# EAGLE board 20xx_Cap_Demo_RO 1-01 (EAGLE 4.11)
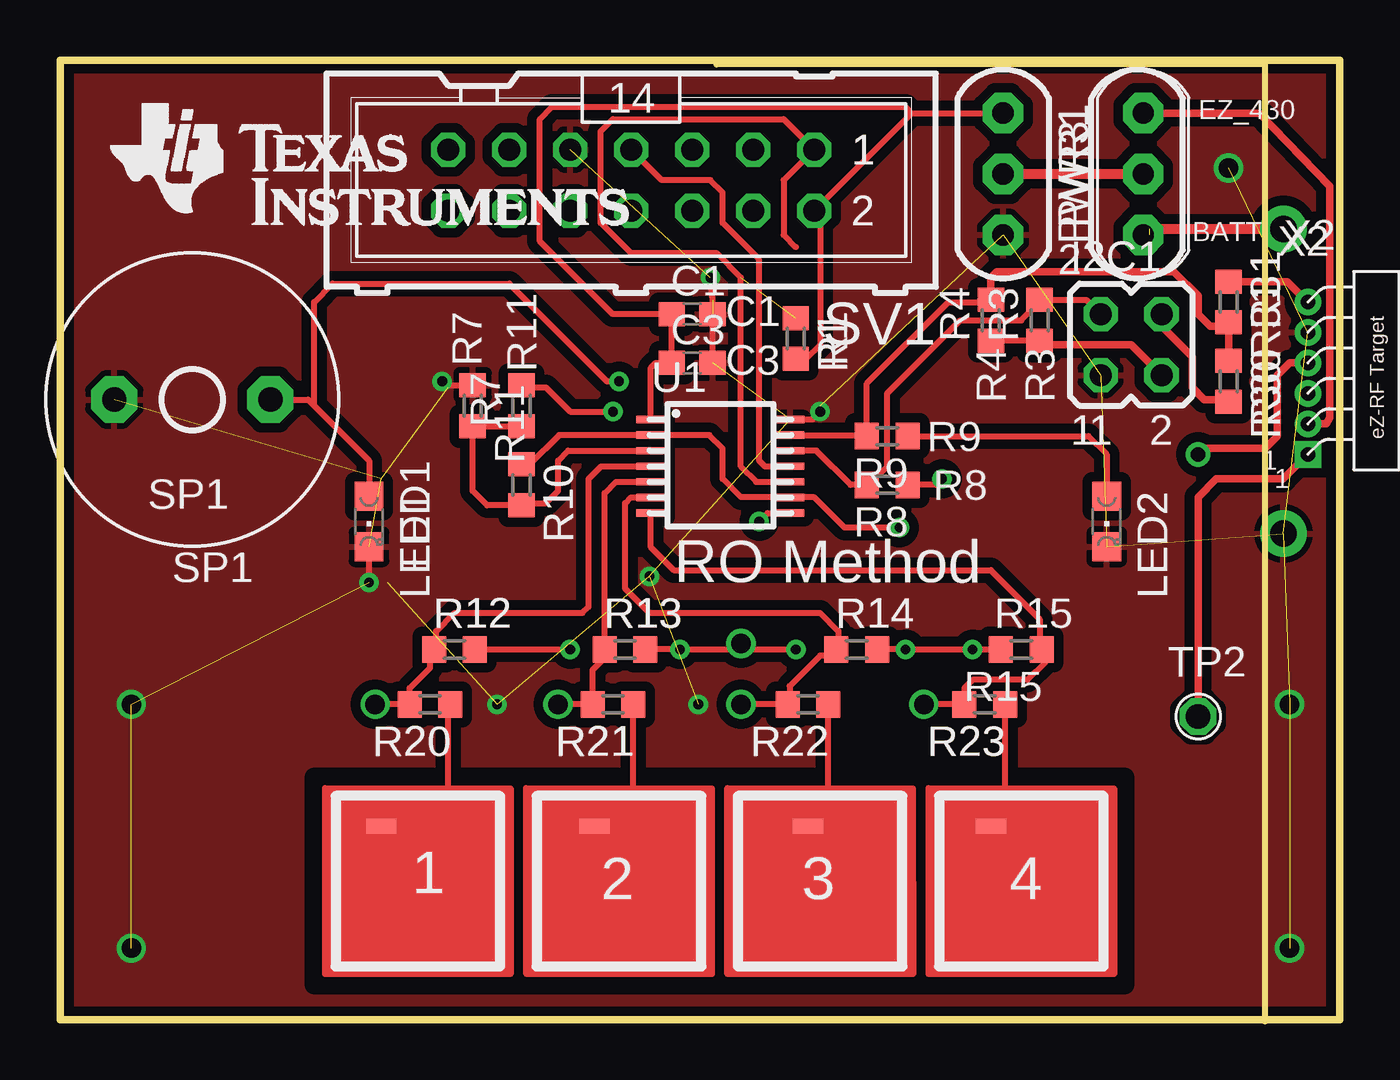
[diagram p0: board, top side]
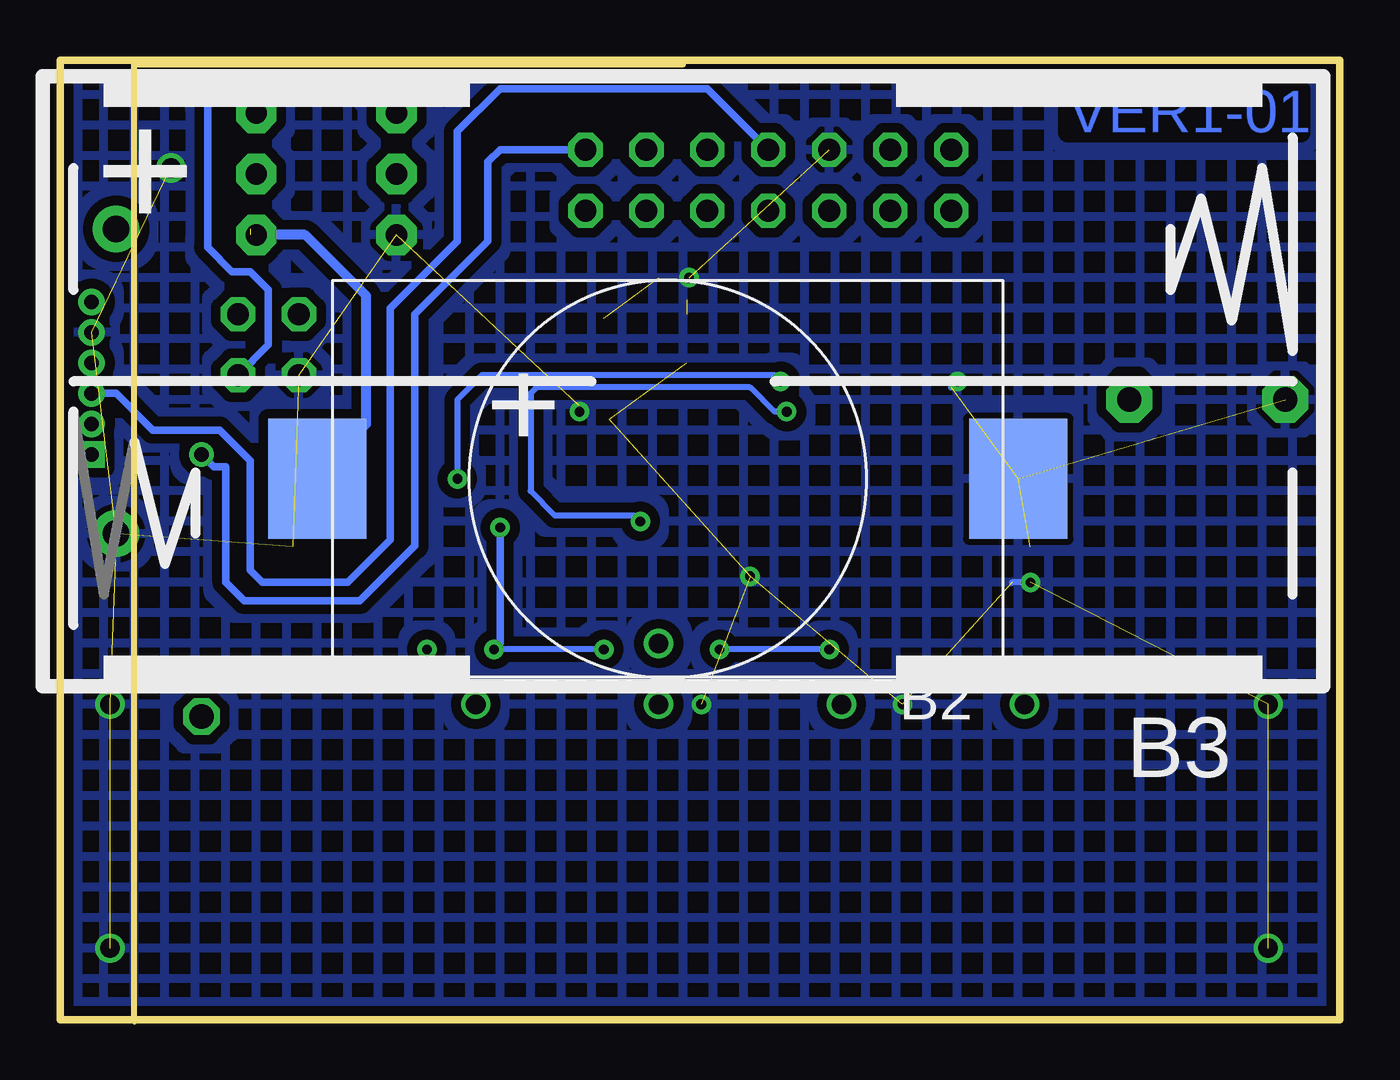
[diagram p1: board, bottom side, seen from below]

Size 53.31 x 39.98 mm. Coordinates in mm from the lower left corner, seen from the top.
Outline: 0,0 53.31,0 53.31,39.98 0,39.98 0,0
Copper layers (1*16): Top 0.035mm / dielectric 1.5mm / Bottom 0.035mm
Design rules "MSP430 PCBExpress ZA 06": minimum track width 8mil, minimum drill 14mil, track to track 8mil, track to pad 8mil, pad to pad 7mil, via to via 10mil, smd to smd 8mil, copper to edge 8mil, drill to drill 8mil, minimum pad ring 10mil, minimum via ring 8mil, stop-mask expansion 8mil, vias tented up to drill 16mil, thermal gap 10mil
Net classes: 1 Analog: width 0.254 mm, drill 0.254 mm; 2 Power: width 0.305 mm, drill 0.254 mm; 3 LCD: width 0.203 mm, drill 0.203 mm; 4 Digital: width 0.203 mm, drill 0.203 mm
Milling: 2 lines

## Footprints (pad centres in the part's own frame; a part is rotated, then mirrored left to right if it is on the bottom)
BA2032SM = smd 4.1 x 5: + 13.97,0; - -15.24,0
KS2468_2 = drill 1.1 pad 1.93 round: + 24.892,-6.35; - 24.892,6.35
C0603 = smd 1.1 x 1: 1 -0.85,0; 2 0.85,0
JP2Q = drill 0.914 octagon: 1 -1.27,-1.27; 2 -1.27,1.27; 3 1.27,-1.27; 4 1.27,1.27
CHIPLED_0805 = smd 1.2 x 1.2: A 0,-1.05; C 0,1.05
X905 = drill 0.889 pad 1.676 octagon: 1 -2.54,0; 2 0,0; 3 2.54,0
R0603 = smd 1 x 1.1: 1 -0.85,0; 2 0.85,0
AL60P = drill 1.016 pad 1.93 octagon: 1 -3.251,0; 2 3.251,0
ML14 = drill 0.914 octagon: 1 -7.62,-1.27; 2 -7.62,1.27; 3 -5.08,-1.27; 4 -5.08,1.27; 5 -2.54,-1.27; 6 -2.54,1.27; 7 0,-1.27; 8 0,1.27; 9 2.54,-1.27; 10 2.54,1.27; 11 5.08,-1.27; 12 5.08,1.27; 13 7.62,-1.27; 14 7.62,1.27
TP = drill 1.016 octagon: 1 0,0
PW14 = smd 0.3 x 1.2: 1 0.322,-1.212; 2 0.972,-1.212; 3 1.622,-1.212; 4 2.272,-1.212; 5 2.922,-1.212; 6 3.572,-1.212; 7 4.222,-1.212; 8 4.222,4.588; 9 3.572,4.588; 10 2.922,4.588; 11 2.272,4.588; 12 1.622,4.588; 13 0.972,4.588; 14 0.322,4.588
4PADSLIDERSMT = smd 1.27 x 0.635: P$1 2.54,6.35; P$2 11.43,6.35; P$3 20.32,6.35; P$4 27.94,6.35
EZ430_RF2500_6 = drill 0.6 pad 1.016 square: 1 0,0 | drill 0.6 pad 1.016 round: 2 0,1.27; 3 0,2.54; 4 0,3.81; 5 0,5.08; 6 0,6.35

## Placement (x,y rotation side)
B2  3V  [BA2032SM]  28.63,22.53 180 bottom
B3  [KS2468_2]  26.09,26.59 180 bottom
C1  0.1uF  [C0603]  26.34,29.39 0 top
C3  1u  [C0603]  26.34,27.36 0 top
I2C1  [JP2Q]  44.63,28.12 0 top
LED1  [CHIPLED_0805]  12.88,20.75 180 top
LED2  [CHIPLED_0805]  43.61,20.75 180 top
PWR1  [X905]  39.29,35.23 270 top
PWR3  [X905]  45.14,35.23 90 top
R1  47k  [R0603]  30.66,28.37 270 top
R3  10k  [R0603]  40.82,29.13 90 top
R4  10k  [R0603]  38.79,29.13 90 top
R7  10k  [R0603]  19.23,25.58 90 top
R8  499  [R0603]  34.47,22.28 180 top
R9  499  [R0603]  34.47,24.31 180 top
R10  10k  [R0603]  19.23,22.28 270 top
R11  10k  [R0603]  17.2,25.58 270 top
R12  100k  [R0603]  16.43,15.42 0 top
R13  100k  [R0603]  23.55,15.42 0 top
R14  100k  [R0603]  33.2,15.42 0 top
R15  100k  [R0603]  40.06,15.42 180 top
R20  0  [R0603]  15.42,13.13 180 top
R21  0  [R0603]  23.04,13.13 180 top
R22  0  [R0603]  31.17,13.13 180 top
R23  0  [R0603]  38.53,13.13 180 top
R30  0  [R0603]  48.69,26.59 270 top
R31  0  [R0603]  48.69,29.9 270 top
SP1  AL60P  [AL60P]  5.51,25.83 180 top
SV1  [ML14]  23.8,34.98 180 top
TP2  [TP]  47.42,12.62 0 top
U1  F20XX  [PW14]  25.83,25.32 270 top
U$5  4PADSLIDER  [4PADSLIDERSMT]  10.85,1.7 0 top
U$8  [TI_LOGO_NEW2]  1.7,31.93 0 top
X2  [EZ430_RF2500_6]  51.99,23.55 0 top

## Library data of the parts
B2 LED1 LED2 PWR1 PWR3 SV1 U1 = F20xx PIR Demo & Eval
B3 R1 R3 R4 R7-R15 R20-R23 R30 R31 = _MSP430
C1 C3 = rcl
I2C1 = jumper
SP1 = buzzer
TP2 = _5438_ATC
U$5 = Touch Pad
U$8 = _ti_logo
X2 = _MSP430_RF

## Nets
CA1: R7.1 R10.2 R11.2 U1.3
CA2: R12.1 R20.2 U1.4
CA3: R13.1 R21.2 U1.5
CA4: R14.1 R22.2 U1.6
CA5: R15.1 R23.2 U1.7
CAOUT: R10.1 R12.2 R13.2 R14.2 R15.2 U1.2 U1.9
GND: B2.- B3.- C1.2 C3.2 I2C1.1 LED1.C LED2.C PWR1.3 R11.1 SP1.2 SV1.9 U1.14 X2.5
N$1: LED1.A R8.1 SP1.1
N$2: LED2.A R9.1
N$4: R20.1 U$5.P$1
N$6: R21.1 U$5.P$2
N$7: R22.1 U$5.P$3
N$8: R23.1 U$5.P$4
N$15: PWR3.3 X2.2
N$17: R31.1 X2.6
N$18: I2C1.4 R30.2
N$22: TP2.1 X2.1
N$24: B2.+ B3.+ PWR3.1
N$25: PWR1.2 PWR3.2
SBWCLK: SV1.7 U1.11 X2.3
SBWDAT: R1.1 SV1.1 U1.10 X2.4
SCL_1: R4.2 R9.2 R30.1 R31.2 U1.13
SDA_1: I2C1.2 R3.2 R8.2 U1.12
V_REF: R7.2 U1.8
VCC: C1.1 C3.1 I2C1.3 PWR1.1 R1.2 R3.1 R4.1 SV1.2 U1.1

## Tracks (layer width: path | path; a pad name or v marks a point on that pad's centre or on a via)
CA1
  Top 0.254: R7.1 19.06,24.73 18.97,24.82 18.89,24.73 R11.2 17.2,22.02 17.79,21.43 R10.2 19.65,21.43 19.74,21.51 20.24,21.51 20.75,22.02 20.75,23.29 21.16,23.7 U1.3
CA2  (via drill 0.81)
  Top 0.254: 15.58,15.33 15.58,15.25 15.42,15.42 15.42,14.66 14.57,13.81 R20.2 v13.13,13.13 13.22,13.22 | U1.4 22.54,23.05 22.02,22.53 22.02,17.2 21.77,16.94 16.43,16.94 15.67,16.18 15.67,15.42 15.58,15.33 | 15.58,15.33 R12.1
CA3  (via drill 0.81)
  Top 0.254: U1.5 23.16,22.4 22.7,21.93 R13.1 22.7,15.25 22.78,15.16 22.19,14.57 R21.2 v20.75,13.13
CA4  (via drill 0.81)
  Top 0.254: 32.18,15.16 32.44,15.16 | 32.35,15.33 32.18,15.16 | U1.6 23.78,21.75 23.55,21.51 23.55,17.96 24.56,16.94 31.67,16.94 32.44,16.18 32.44,15.42 32.35,15.33 | 32.35,15.33 R14.1 | 32.18,15.16 31.67,15.16 30.4,13.89 30.4,13.39 R22.2 28.63,13.13 28.46,13.22 v28.37,13.13
CA5  (via drill 0.81)
  Top 0.254: U1.7 24.62,19.68 25.58,18.72 38.79,18.72 40.82,16.69 40.82,15.67 40.91,15.58 R15.1 40.91,15.25 40.82,15.16 41.07,14.91 40.31,14.15 38.02,14.15 37.68,13.81 R23.2 v35.99,13.13 36.08,13.22
CAOUT  (via drill 0.41, 0.81)
  Top 0.254: 34.21,15.42 R14.2 v35.23,15.42 v38.02,15.42 R15.2 | v34.98,20.5 32.69,20.5 31.44,21.75 U1.9 29.91,21.75 29.9,21.77 28.37,21.77 27.61,22.53 27.61,23.8 27.06,24.35 U1.2 20.8,24.35 19.57,23.13 R10.1 | R12.2 v21.26,15.42 | 28.37,15.42 v25.83,15.42 R13.2 24.31,15.42 | 28.37,15.42 v30.66,15.42 | 28.37,15.42 v28.37,15.67
  Bottom 0.254: v30.66,15.42 v35.23,15.42 | v21.26,15.42 v25.83,15.42
  Bottom 0.305: v34.98,20.5 34.98,15.67 v35.23,15.42
GND  (via drill 0.41, 0.81)  (20 unrouted)
  Top 0.254: 27.19,29.05 27.1,29.13 27.19,29.22 C1.2 | v27.1,30.91 27.19,29.98 C3.2 | v31.67,25.32 31.35,25 U1.14 | R11.1 16.09,26.43 v15.93,26.59 | v12.88,18.21 LED1.C
  Bottom 0.254: v31.67,25.32 31.67,25.58 | 16.18,26.34 v15.93,26.59 | v12.88,18.21 13.64,18.21
  other vias: 48.69,35.48 51.23,2.97 51.23,13.13 26.59,13.13 24.56,18.47 18.21,13.13 2.97,2.97 2.97,13.13
  pour Top (isolate 0.406): 0.69,0.43 0.69,39.55 53.14,39.55 53.14,0.43
  pour Bottom (isolate 0.406, hatched): 0.69,39.55 0.69,0.43 53.09,0.48 53.09,39.6
N$1  (via drill 0.41)
  Top 0.254: v23.29,26.59 22.78,26.59 18.72,30.66 11.35,30.66 10.59,29.9 10.59,25.58 | 10.59,25.58 12.88,23.29 LED1.A | v36.75,22.53 36.5,22.28 R8.1 | SP1.1 10.34,25.83 10.59,25.58
  Bottom 0.254: v23.29,26.59 23.55,26.85 35.74,26.85 36.75,25.83 v36.75,22.53
N$2
  Top 0.254: R9.1 42.85,24.31 43.61,23.55 LED2.A
N$4
  Top 0.254: R20.1 16.18,12.88 16.18,9.58 14.66,8.05 U$5.P$1
N$6
  Top 0.254: R21.1 23.89,8.65 23.8,8.56 24.56,9.07 23.55,8.05 U$5.P$2
N$7
  Top 0.254: 31.93,8.31 32.44,8.81 | 31.93,8.31 32.44,8.56 32.02,8.98 R22.1 | 31.93,8.31 31.67,8.05 U$5.P$3
N$8
  Top 0.254: R23.1 39.38,8.73 39.55,8.56 41.07,8.81 40.31,8.05 U$5.P$4
N$15
  Top 0.305: X2.2 52.76,24.82 52.91,25.07 52.91,34.72 49.96,37.77 PWR3.3
N$17
  Top 0.305: R31.1 51.14,30.75 X2.6
N$18
  Top 0.305: I2C1.4 45.9,28.88 47.17,27.61 47.17,26.34 47.68,25.83 48.69,25.83 R30.2
N$22
  Top 0.305: X2.1 50.98,22.53 48.18,22.53 47.42,21.77 TP2.1
N$24  (1 unrouted)
  Top 0.406: B3.+ 45.39,32.94 PWR3.1
  Bottom 0.406: B2.+ 42.6,22.78 40.56,24.82 40.56,30.15 43.1,32.69 45.39,32.69
N$25
  Top 0.406: PWR1.2 PWR3.2
SBWCLK
  Top 0.254: U1.11 29.37,23.05 29.13,23.29 29.13,31.67 27.61,33.2 27.61,34.47 27.1,34.98 25.07,34.98 SV1.7
  Bottom 0.305: SV1.7 26.34,38.79 34.98,38.79 36.75,37.01 36.75,32.44 39.55,29.64 39.55,19.99 41.33,18.21 44.88,18.21 45.39,18.72 45.39,23.29 46.66,24.56 49.45,24.56 50.98,26.09 X2.3
SBWDAT  (via drill 0.61)  (1 unrouted)
  Top 0.254: U1.10 29.01,22.4 28.37,23.04 28.37,30.91 27.36,31.93 23.8,31.93 22.53,33.2 22.53,37.01 23.04,37.52 30.15,37.52 SV1.1 30.15,34.98 30.15,32.69 30.66,32.18
  Top 0.305: X2.4 51.23,27.36 50.72,26.85 50.72,24.31 50.22,23.8 47.68,23.8 v47.42,23.55
  Bottom 0.305: SV1.1 34.98,36.25 35.48,35.74 35.48,32.44 38.53,29.39 38.53,19.74 40.82,17.45 45.64,17.45 46.41,18.21 46.41,23.04 46.91,23.04 v47.42,23.55
SCL_1
  Top 0.254: U1.13 33.27,24.35 | 33.27,24.35 33.41,24.35 33.45,24.31 | 33.3,24.31 33.22,24.31 | 33.22,24.31 33.2,24.31 | 33.22,24.31 33.25,24.28 33.22,24.28 | 33.22,24.28 33.2,24.28 | 33.22,24.28 33.27,24.28 33.3,24.31 | 33.32,24.31 R9.2 33.62,26.51 37.01,29.9 38.28,29.9 38.37,29.98 | 33.32,24.31 33.3,24.31 | 33.27,24.35 33.27,24.36 33.32,24.31
  Top 0.305: R4.2 38.79,30.91 39.04,31.17 46.41,31.17 47.42,30.15 47.42,29.39 47.93,28.88 48.44,28.88 48.69,29.13 | 48.69,29.13 R31.2 | 48.69,29.13 R30.1 | 38.37,29.98 R4.2 | R4.2 38.79,29.9
SDA_1
  Top 0.254: U1.12 31.52,23.7 32.94,22.28 R8.2 33.71,22.28 34.47,23.04 34.47,26.09 37.52,29.13 40.06,29.13 40.82,29.9 R3.2 42.76,29.98 I2C1.2
V_REF  (via drill 0.41)
  Top 0.254: v29.13,20.75 29.48,21.1 U1.8 | v23.04,25.32 21.26,25.32 20.24,26.34 19.48,26.34 19.39,26.43 R7.2
  Bottom 0.254: v23.04,25.32 23.55,25.32 24.56,26.34 33.45,26.34 33.71,26.09 33.71,22.02 32.69,21.01 29.39,21.01 v29.13,20.75
VCC
  Top 0.254: R4.1 40.48,28.28 40.56,28.37 40.65,28.28 R3.1 40.91,28.28 41.07,28.12 | R1.2 31.08,27.52 31.67,28.12 31.67,33.45 SV1.2 35.48,37.77 | U1.1 24.62,27.16 24.82,27.36 25.58,27.36 | 25.58,27.36 C3.1 | 35.48,37.77 PWR1.1 | 35.48,37.77 35.23,38.02 20.5,38.02 19.99,37.52 19.99,32.44 23.04,29.39 C1.1 25.49,27.44 25.58,27.36
  Top 0.305: 41.07,28.12 44.63,28.12 I2C1.3
  Bottom 0.305: I2C1.3 44.63,28.12 44.63,30.4 45.39,31.17 46.15,31.17 47.17,32.18 47.17,38.28 46.41,39.04 40.56,39.04 PWR1.1

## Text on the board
Bottom: VER1-01
_tplace: PWR1 | EZ_430 | 1 | 2 | BATT | X2 | 2 | R11 | R1 | C1 | R4 | R31 | R7 | U1 | C3 | R9 | R3 | R30 | LED1 | R10 | 1 | SP1 | R8 | LED2 | 1 | RO Method | R15 | R12 | R13 | R14 | R20 | R21 | R22 | R23 | 1 | 2 | 3 | 4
